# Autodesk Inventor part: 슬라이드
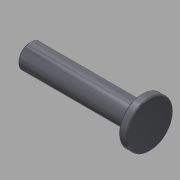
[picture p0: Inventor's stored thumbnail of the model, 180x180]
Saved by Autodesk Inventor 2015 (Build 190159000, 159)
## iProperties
Created: 2015-10
Part Number: 슬라이드
Document SubType Name: Modeling
Designer: mdu
Density: 7.86 g/cm^3
Material: 강철, 연강
Appearance: 강철 - 광택
Mass: 954.83 g
Surface Area: 210.251 cm^2
Volume: 121.48 cm^3
Author: mdu
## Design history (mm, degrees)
sketch "스케치1"
  geometry: L1 (-75, 162)-(-75, 58) reference; L2 (-148, 110)-(2, 110); L3 (-148, 110)-(-148, 125); L4 (-148, 125)-(-8, 125); L5 (-8, 125)-(-8, 139); L6 (-8, 139)-(2, 139); L7 (2, 139)-(2, 110); 2 further points
  constraints: 12 end point, 3 parallel, 3 perpendicular, 1 midpoint, 1 point on line
  dimensions: "d0" = 58 diameter of L6 L2; "d1" = 30 diameter of L4 L2; "d2" = 10 distance of L5.end L6.end; "d3" = 150 distance of L2.start L2.end; "d4" = 73 distance between parallel lines of L3 L1
revolve "회전1" sketch "스케치1" stored, may be unused: angle "d5" = 90 deg
hole "구멍1" diameter "d11" = 13.376; stored, may be unused: countersink angle "d15" = 90 deg, drill point angle "d17" = 118 deg; dims "d9" = 10, "d10" = 10, "d12" = 22, "d13" = 4, "d14" = 2, "d16" = 25
chamfer "모따기1" distance "d6" = 1; stored, may be unused: second distance "d7" = 2, angle "d8" = 45 deg
node "솔리드1"
node "참조1"
